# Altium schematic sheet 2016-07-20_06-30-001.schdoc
size 223 x 127 mm; SheetNumber: 1; SheetTotal: 1
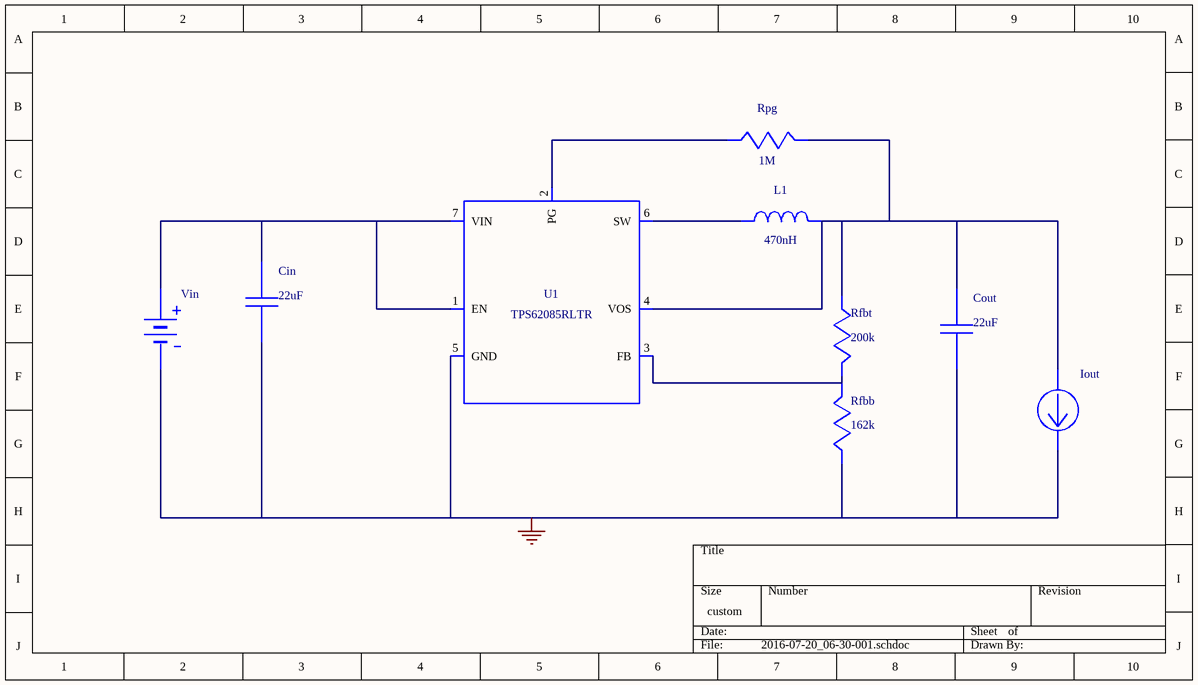
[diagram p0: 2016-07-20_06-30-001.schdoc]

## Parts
Cin  value 22uF  (hidden comment: LMK212BJ226MG-T)
Cout  value 22uF  (hidden comment: JMK212BJ226KG-T)
Iout  WB_CURRENT_LOAD  (value not drawn)
L1  value 470nH  (hidden comment: LQM21PNR47MC0D)
Rfbb  value 162k  (hidden comment: CRCW0402162KFKED)
Rfbt  value 200k  (hidden comment: CRCW0402200KFKED)
Rpg  value 1M  (hidden comment: CRCW04021M00FKED)
U1  TPS62085RLTR
Vin  WB_BATTERY  (value not drawn)

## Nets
0: Cin.2 Cout.2 Iout.2(-) Rfbb.2 U1.5(GND) Vin.2(-)
NetCin_1: Cin.1 U1.1(EN) U1.7(VIN) Vin.1(+)
NetCout_1: Cout.1 Iout.1(+) L1.2 Rfbt.2 Rpg.1 U1.4(VOS)
NetL1_1: L1.1 U1.6(SW)
NetRfbb_1: Rfbb.1 Rfbt.1 U1.3(FB)
NetRpg_2: Rpg.2 U1.2(PG)

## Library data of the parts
Cin = LMK212BJ226MG-T: Manufacturer Name: Taiyo Yuden
Cout = JMK212BJ226KG-T: Manufacturer Name: Taiyo Yuden
L1 = LQM21PNR47MC0D: Manufacturer Name: MuRata
Rfbb = CRCW0402162KFKED: Manufacturer Name: Vishay-Dale
Rfbt = CRCW0402200KFKED: Manufacturer Name: Vishay-Dale
Rpg = CRCW04021M00FKED: Manufacturer Name: Vishay-Dale
U1 = TPS62085RLTR: Manufacturer Name: Texas Instruments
